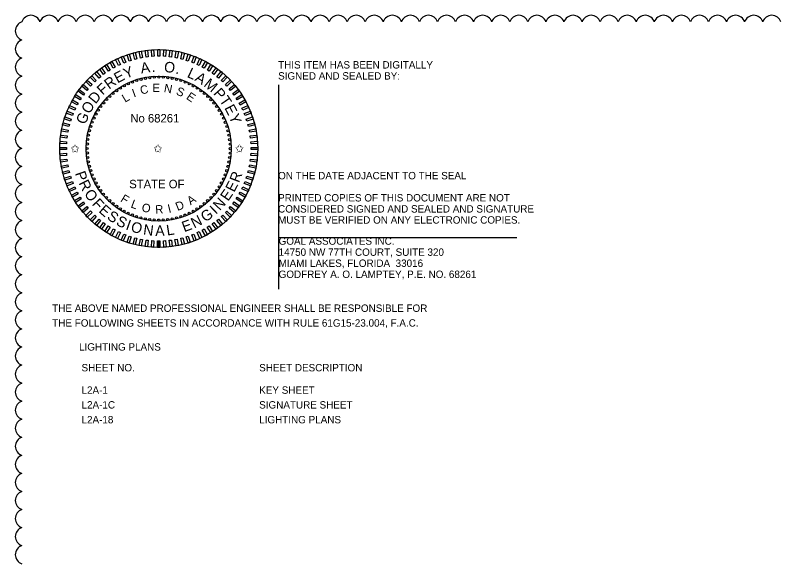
# Model space of a CAD drawing. Extents: x -811 to -790, y -2284 to -2178.
# Drawn here: x -810.85 to -803.6, y -2224.81 to -2219.62 of the extents above; entities that cross this region are included whole.
import ezdxf

# ---------------------------------------------------------------- set-up
doc = ezdxf.new("R2010")
doc.units = 0
for name, color, linetype in [('AdhocPoint_dp', 7, 'Continuous'), ('PlotBorder_dp', 7, 'Continuous'), ('TextMinor', 7, 'Continuous'), ('TextMisc', 7, 'Continuous'), ('TextShtNo', 7, 'Continuous'), ('TextTitle', 7, 'Continuous')]:
    doc.layers.add(name, color=color, linetype=linetype)

msp = doc.modelspace()

# ---------------------------------------------------------------- linework, layer by layer
at = {"layer": 'AdhocPoint_dp'}
for p, q in [((-808.3546, -2220.2766), (-808.3546, -2222.2113)), ((-808.3546, -2221.7213), (-806.0979, -2221.7213))]:
    msp.add_line(p, q, dxfattribs=at)
at = {"layer": 'TextMinor'}
for radius in [0.9375, 0.6875]:
    msp.add_circle((-809.4901, -2220.88), radius, dxfattribs=at)
at = {"layer": 'TextShtNo'}
for p, q in [((-809.5001, -2221.8175), (-809.5003, -2221.755)), ((-809.4901, -2221.8175), (-809.4903, -2221.755)), ((-809.4801, -2221.8174), (-809.4803, -2221.7549))]:
    msp.add_line(p, q, dxfattribs=at)
for points in [[(-809.6441, -2220.0185), (-809.6639, -2220.0223), (-809.6756, -2219.961), (-809.6558, -2219.9572)], [(-809.5897, -2220.0105), (-809.6097, -2220.0131), (-809.6175, -2219.9511), (-809.5975, -2219.9486)], [(-809.5349, -2220.006), (-809.555, -2220.0073), (-809.559, -2219.945), (-809.5388, -2219.9437)], [(-809.4799, -2220.0049), (-809.5001, -2220.0049), (-809.5001, -2219.9425), (-809.4799, -2219.9425)], [(-809.425, -2220.0073), (-809.4452, -2220.006), (-809.4412, -2219.9437), (-809.4211, -2219.945)], [(-809.3703, -2220.0131), (-809.3904, -2220.0106), (-809.3825, -2219.9486), (-809.3625, -2219.9512)], [(-809.3162, -2220.0223), (-809.336, -2220.0186), (-809.3243, -2219.9572), (-809.3045, -2219.961)], [(-809.8535, -2220.0839), (-809.8717, -2220.0925), (-809.8983, -2220.036), (-809.8801, -2220.0274)], [(-809.8028, -2220.0626), (-809.8215, -2220.0701), (-809.8445, -2220.012), (-809.8258, -2220.0046)], [(-809.7508, -2220.0446), (-809.77, -2220.0508), (-809.7893, -2219.9915), (-809.7701, -2219.9852)], [(-809.6979, -2220.0299), (-809.7174, -2220.0349), (-809.7329, -2219.9744), (-809.7134, -2219.9694)], [(-809.2626, -2220.0349), (-809.2822, -2220.0299), (-809.2667, -2219.9695), (-809.2471, -2219.9745)], [(-809.21, -2220.0509), (-809.2292, -2220.0447), (-809.2099, -2219.9853), (-809.1907, -2219.9915)], [(-809.1585, -2220.0701), (-809.1773, -2220.0627), (-809.1543, -2220.0046), (-809.1355, -2220.0121)], [(-809.1083, -2220.0925), (-809.1266, -2220.0839), (-809.1, -2220.0274), (-809.0817, -2220.036)], [(-809.9504, -2220.1357), (-809.9674, -2220.1465), (-810.0009, -2220.0938), (-809.9838, -2220.083)], [(-809.9027, -2220.1083), (-809.9204, -2220.118), (-809.9505, -2220.0633), (-809.9328, -2220.0535)], [(-809.0596, -2220.1181), (-809.0773, -2220.1083), (-809.0473, -2220.0536), (-809.0296, -2220.0634)], [(-809.0127, -2220.1466), (-809.0297, -2220.1358), (-808.9962, -2220.0831), (-808.9792, -2220.0939)], [(-810.04, -2220.1992), (-810.0556, -2220.2121), (-810.0954, -2220.164), (-810.0798, -2220.1511)], [(-809.9962, -2220.1661), (-810.0125, -2220.1779), (-810.0492, -2220.1274), (-810.0329, -2220.1155)], [(-808.9676, -2220.178), (-808.9839, -2220.1662), (-808.9472, -2220.1156), (-808.9308, -2220.1275)], [(-808.9245, -2220.2122), (-808.9401, -2220.1994), (-808.9003, -2220.1512), (-808.8847, -2220.1641)], [(-810.121, -2220.2735), (-810.1348, -2220.2882), (-810.1804, -2220.2455), (-810.1665, -2220.2308)], [(-810.0817, -2220.2351), (-810.0964, -2220.2489), (-810.1392, -2220.2034), (-810.1244, -2220.1896)], [(-808.8837, -2220.2491), (-808.8984, -2220.2352), (-808.8557, -2220.1897), (-808.841, -2220.2035)], [(-808.8453, -2220.2884), (-808.8591, -2220.2737), (-808.8136, -2220.2309), (-808.7998, -2220.2456)], [(-810.192, -2220.3574), (-810.2039, -2220.3737), (-810.2544, -2220.337), (-810.2426, -2220.3207)], [(-810.1579, -2220.3143), (-810.1707, -2220.3299), (-810.2188, -2220.2901), (-810.206, -2220.2745)], [(-808.8094, -2220.33), (-808.8223, -2220.3145), (-808.7742, -2220.2747), (-808.7613, -2220.2902)], [(-808.7762, -2220.3739), (-808.7881, -2220.3575), (-808.7376, -2220.3208), (-808.7257, -2220.3372)], [(-810.2235, -2220.4025), (-810.2343, -2220.4195), (-810.287, -2220.3861), (-810.2762, -2220.369)], [(-808.7459, -2220.4197), (-808.7567, -2220.4026), (-808.7039, -2220.3692), (-808.6931, -2220.3862)], [(-810.252, -2220.4495), (-810.2617, -2220.4672), (-810.3164, -2220.4371), (-810.3067, -2220.4194)], [(-808.7184, -2220.4673), (-808.7281, -2220.4496), (-808.6734, -2220.4196), (-808.6637, -2220.4373)], [(-810.3, -2220.5484), (-810.3074, -2220.5671), (-810.3654, -2220.5441), (-810.358, -2220.5254)], [(-810.2775, -2220.4982), (-810.2861, -2220.5164), (-810.3426, -2220.4898), (-810.334, -2220.4716)], [(-808.694, -2220.5166), (-808.7026, -2220.4983), (-808.6461, -2220.4718), (-808.6375, -2220.49)], [(-808.6728, -2220.5673), (-808.6802, -2220.5485), (-808.6222, -2220.5256), (-808.6147, -2220.5443)], [(-810.3192, -2220.5999), (-810.3254, -2220.6191), (-810.3848, -2220.5998), (-810.3786, -2220.5806)], [(-808.6548, -2220.6192), (-808.661, -2220.6), (-808.6016, -2220.5808), (-808.5954, -2220.5999)], [(-810.3351, -2220.6525), (-810.3401, -2220.672), (-810.4006, -2220.6565), (-810.3956, -2220.637)], [(-808.64, -2220.6722), (-808.6451, -2220.6527), (-808.5846, -2220.6371), (-808.5796, -2220.6567)], [(-810.357, -2220.7602), (-810.3595, -2220.7802), (-810.4215, -2220.7724), (-810.4189, -2220.7524)], [(-810.3477, -2220.706), (-810.3515, -2220.7258), (-810.4129, -2220.7141), (-810.4091, -2220.6943)], [(-808.6287, -2220.726), (-808.6325, -2220.7062), (-808.5711, -2220.6945), (-808.5673, -2220.7143)], [(-808.6207, -2220.7804), (-808.6232, -2220.7604), (-808.5613, -2220.7525), (-808.5588, -2220.7726)], [(-810.3628, -2220.8148), (-810.3641, -2220.835), (-810.4264, -2220.8311), (-810.4251, -2220.8109)], [(-808.6162, -2220.8352), (-808.6174, -2220.815), (-808.5551, -2220.8111), (-808.5539, -2220.8313)], [(-810.3652, -2220.8698), (-810.3652, -2220.89), (-810.4276, -2220.89), (-810.4276, -2220.8698)], [(-808.6151, -2220.8901), (-808.6151, -2220.87), (-808.5527, -2220.87), (-808.5527, -2220.8901)], [(-810.3641, -2220.9247), (-810.3628, -2220.9449), (-810.4251, -2220.9488), (-810.4264, -2220.9287)], [(-808.6175, -2220.9451), (-808.6162, -2220.9249), (-808.5539, -2220.9288), (-808.5551, -2220.949)], [(-810.3595, -2220.9795), (-810.357, -2220.9995), (-810.4189, -2221.0074), (-810.4215, -2220.9873)], [(-810.3516, -2221.0339), (-810.3478, -2221.0537), (-810.4091, -2221.0654), (-810.4129, -2221.0456)], [(-808.6325, -2221.0539), (-808.6287, -2221.0341), (-808.5674, -2221.0458), (-808.5712, -2221.0656)], [(-808.6233, -2220.9997), (-808.6207, -2220.9797), (-808.5588, -2220.9875), (-808.5613, -2221.0076)], [(-810.3402, -2221.0877), (-810.3352, -2221.1073), (-810.3957, -2221.1228), (-810.4007, -2221.1032)], [(-808.6451, -2221.1074), (-808.6401, -2221.0879), (-808.5796, -2221.1034), (-808.5846, -2221.123)], [(-810.3255, -2221.1407), (-810.3192, -2221.1599), (-810.3786, -2221.1792), (-810.3849, -2221.16)], [(-810.3075, -2221.1926), (-810.3, -2221.2114), (-810.3581, -2221.2344), (-810.3655, -2221.2156)], [(-808.6803, -2221.2115), (-808.6729, -2221.1928), (-808.6148, -2221.2158), (-808.6222, -2221.2345)], [(-808.6611, -2221.16), (-808.6548, -2221.1408), (-808.5954, -2221.1601), (-808.6017, -2221.1793)], [(-810.2862, -2221.2433), (-810.2776, -2221.2616), (-810.3341, -2221.2882), (-810.3427, -2221.2699)], [(-808.7027, -2221.2617), (-808.6941, -2221.2435), (-808.6376, -2221.2701), (-808.6462, -2221.2883)], [(-810.2618, -2221.2926), (-810.2521, -2221.3103), (-810.3068, -2221.3403), (-810.3165, -2221.3227)], [(-808.7282, -2221.3104), (-808.7185, -2221.2927), (-808.6638, -2221.3228), (-808.6735, -2221.3405)], [(-810.2344, -2221.3402), (-810.2236, -2221.3573), (-810.2763, -2221.3907), (-810.2871, -2221.3737)], [(-810.204, -2221.386), (-810.1922, -2221.4024), (-810.2427, -2221.4391), (-810.2545, -2221.4227)], [(-808.7882, -2221.4025), (-808.7763, -2221.3862), (-808.7258, -2221.4229), (-808.7377, -2221.4392)], [(-808.7568, -2221.3574), (-808.746, -2221.3404), (-808.6932, -2221.3738), (-808.704, -2221.3909)], [(-810.1708, -2221.4299), (-810.158, -2221.4454), (-810.2061, -2221.4852), (-810.2189, -2221.4697)], [(-810.135, -2221.4715), (-810.1211, -2221.4862), (-810.1667, -2221.529), (-810.1805, -2221.5143)], [(-808.8592, -2221.4864), (-808.8454, -2221.4717), (-808.7999, -2221.5144), (-808.8137, -2221.5291)], [(-808.8224, -2221.4456), (-808.8095, -2221.43), (-808.7614, -2221.4698), (-808.7743, -2221.4854)], [(-810.0965, -2221.5109), (-810.0818, -2221.5247), (-810.1246, -2221.5702), (-810.1393, -2221.5564)], [(-810.0557, -2221.5477), (-810.0402, -2221.5606), (-810.08, -2221.6087), (-810.0955, -2221.5958)], [(-808.9402, -2221.5607), (-808.9247, -2221.5478), (-808.8848, -2221.5959), (-808.9004, -2221.6088)], [(-808.8985, -2221.5248), (-808.8838, -2221.511), (-808.8411, -2221.5565), (-808.8558, -2221.5703)], [(-810.0127, -2221.5819), (-809.9964, -2221.5937), (-810.0331, -2221.6443), (-810.0494, -2221.6324)], [(-809.9676, -2221.6133), (-809.9505, -2221.6241), (-809.984, -2221.6768), (-810.001, -2221.666)], [(-809.0299, -2221.6242), (-809.0128, -2221.6134), (-808.9794, -2221.6661), (-808.9964, -2221.6769)], [(-808.984, -2221.5939), (-808.9677, -2221.582), (-808.931, -2221.6325), (-808.9473, -2221.6444)], [(-809.9206, -2221.6418), (-809.9029, -2221.6516), (-809.933, -2221.7063), (-809.9507, -2221.6966)], [(-809.8719, -2221.6674), (-809.8536, -2221.676), (-809.8802, -2221.7325), (-809.8985, -2221.7239)], [(-809.8217, -2221.6898), (-809.8029, -2221.6972), (-809.8259, -2221.7553), (-809.8447, -2221.7478)], [(-809.1775, -2221.6973), (-809.1587, -2221.6899), (-809.1357, -2221.7479), (-809.1545, -2221.7553)], [(-809.1268, -2221.676), (-809.1085, -2221.6674), (-809.0819, -2221.7239), (-809.1002, -2221.7325)], [(-809.0775, -2221.6517), (-809.0598, -2221.6419), (-809.0297, -2221.6966), (-809.0474, -2221.7064)], [(-809.7702, -2221.709), (-809.751, -2221.7152), (-809.7703, -2221.7746), (-809.7895, -2221.7684)], [(-809.7176, -2221.725), (-809.698, -2221.73), (-809.7136, -2221.7905), (-809.7331, -2221.7854)], [(-809.6641, -2221.7376), (-809.6443, -2221.7414), (-809.656, -2221.8027), (-809.6758, -2221.7989)], [(-809.6099, -2221.7468), (-809.5899, -2221.7493), (-809.5977, -2221.8113), (-809.6177, -2221.8088)], [(-809.5552, -2221.7526), (-809.5351, -2221.7539), (-809.539, -2221.8162), (-809.5592, -2221.8149)], [(-809.5003, -2221.755), (-809.4801, -2221.755), (-809.4801, -2221.8174), (-809.5003, -2221.8174)], [(-809.4453, -2221.7539), (-809.4252, -2221.7526), (-809.4213, -2221.8149), (-809.4414, -2221.8162)], [(-809.3906, -2221.7494), (-809.3705, -2221.7468), (-809.3627, -2221.8088), (-809.3827, -2221.8113)], [(-809.3362, -2221.7414), (-809.3163, -2221.7376), (-809.3046, -2221.7989), (-809.3245, -2221.8027)], [(-809.2824, -2221.73), (-809.2628, -2221.725), (-809.2473, -2221.7855), (-809.2668, -2221.7905)], [(-809.2294, -2221.7153), (-809.2102, -2221.7091), (-809.1909, -2221.7685), (-809.2101, -2221.7747)]]:
    msp.add_lwpolyline(points, close=True, dxfattribs=at)
for centre in [(-809.739, -2220.2499), (-809.6989, -2220.2355), (-809.6581, -2220.2236), (-809.6165, -2220.2144), (-809.5745, -2220.2078), (-809.5321, -2220.2038), (-809.4896, -2220.2025), (-809.447, -2220.2039), (-809.4047, -2220.2079), (-809.3626, -2220.2146), (-809.3211, -2220.2239), (-809.2802, -2220.2358), (-809.2402, -2220.2503), (-809.8879, -2220.3315), (-809.8527, -2220.3076), (-809.816, -2220.286), (-809.7781, -2220.2667), (-809.2012, -2220.2672), (-809.1633, -2220.2866), (-809.1266, -2220.3083), (-809.0915, -2220.3322), (-809.9535, -2220.3857), (-809.9215, -2220.3576), (-809.0579, -2220.3583), (-809.026, -2220.3865), (-810.0118, -2220.4477), (-809.9836, -2220.4158), (-808.9959, -2220.4166), (-808.9678, -2220.4486), (-810.0618, -2220.5165), (-810.0379, -2220.4813), (-808.9417, -2220.4822), (-808.9178, -2220.5174), (-810.1029, -2220.591), (-810.0835, -2220.5531), (-808.8962, -2220.5541), (-808.8769, -2220.592), (-810.1343, -2220.6701), (-810.1198, -2220.63), (-808.86, -2220.6311), (-808.8456, -2220.6711), (-810.1555, -2220.7525), (-810.1462, -2220.7109), (-808.8338, -2220.712), (-808.8245, -2220.7536), (-810.1662, -2220.8369), (-810.1622, -2220.7945), (-808.8179, -2220.7956), (-808.814, -2220.838), (-810.1676, -2220.8794), (-808.8127, -2220.8805), (-810.1663, -2220.9219), (-810.1623, -2220.9643), (-808.8181, -2220.9654), (-808.814, -2220.9231), (-810.1557, -2221.0063), (-810.1464, -2221.0479), (-808.8341, -2221.049), (-808.8248, -2221.0075), (-810.1346, -2221.0888), (-810.1202, -2221.1288), (-808.8604, -2221.1299), (-808.846, -2221.0898), (-810.1034, -2221.1679), (-808.8774, -2221.1689), (-810.0841, -2221.2058), (-810.0624, -2221.2425), (-808.9184, -2221.2434), (-808.8967, -2221.2068), (-810.0385, -2221.2777), (-810.0125, -2221.3114), (-809.9844, -2221.3433), (-808.9967, -2221.3441), (-808.9685, -2221.3122), (-808.9424, -2221.2786), (-809.9543, -2221.3734), (-809.9224, -2221.4016), (-809.0587, -2221.4023), (-809.0268, -2221.3742), (-809.8888, -2221.4277), (-809.8536, -2221.4517), (-809.817, -2221.4734), (-809.7791, -2221.4927), (-809.2022, -2221.4932), (-809.1642, -2221.4739), (-809.1276, -2221.4523), (-809.0924, -2221.4284), (-809.74, -2221.5096), (-809.7, -2221.5241), (-809.6591, -2221.536), (-809.6176, -2221.5453), (-809.5756, -2221.552), (-809.5332, -2221.5561), (-809.4901, -2221.5575), (-809.4481, -2221.5561), (-809.4058, -2221.5522), (-809.3637, -2221.5455), (-809.3222, -2221.5363), (-809.2813, -2221.5244), (-809.2413, -2221.5101)]:
    msp.add_circle(centre, 0.01, dxfattribs=at)
at = {"layer": 'TextTitle'}
for centre, start, end in [((-810.7002, -2219.707), 17.5, 162.5), ((-810.5291, -2219.707), 17.5, 162.5), ((-810.358, -2219.707), 17.5, 162.5), ((-810.1868, -2219.707), 17.5, 162.5), ((-810.0157, -2219.707), 17.5, 162.5), ((-809.8446, -2219.707), 17.5, 162.5), ((-809.6735, -2219.707), 17.5, 162.5), ((-809.5024, -2219.707), 17.5, 162.5), ((-809.3312, -2219.707), 17.5, 162.5), ((-809.1601, -2219.707), 17.5, 162.5), ((-808.989, -2219.707), 17.5, 162.5), ((-808.8179, -2219.707), 17.5, 162.5), ((-808.6467, -2219.707), 17.5, 162.5), ((-808.4756, -2219.707), 17.5, 162.5), ((-808.3045, -2219.707), 17.5, 162.5), ((-808.1334, -2219.707), 17.5, 162.5), ((-807.9622, -2219.707), 17.5, 162.5), ((-807.7911, -2219.707), 17.5, 162.5), ((-807.62, -2219.707), 17.5, 162.5), ((-807.4489, -2219.707), 17.5, 162.5), ((-807.2778, -2219.707), 17.5, 162.5), ((-807.1066, -2219.707), 17.5, 162.5), ((-806.9355, -2219.707), 17.5, 162.5), ((-806.7644, -2219.707), 17.5, 162.5), ((-806.5933, -2219.707), 17.5, 162.5), ((-806.4221, -2219.707), 17.5, 162.5), ((-806.251, -2219.707), 17.5, 162.5), ((-806.0799, -2219.707), 17.5, 162.5), ((-805.9088, -2219.707), 17.5, 162.5), ((-805.7377, -2219.707), 17.5, 162.5), ((-805.5665, -2219.707), 17.5, 162.5), ((-805.3954, -2219.707), 17.5, 162.5), ((-805.2243, -2219.707), 17.5, 162.5), ((-805.0532, -2219.707), 17.5, 162.5), ((-804.882, -2219.707), 17.5, 162.5), ((-804.7109, -2219.707), 17.5, 162.5), ((-804.5398, -2219.707), 17.5, 162.5), ((-804.3687, -2219.707), 17.5, 162.5), ((-804.1976, -2219.707), 17.5, 162.5), ((-804.0264, -2219.707), 17.5, 162.5), ((-803.8553, -2219.707), 17.5, 162.5), ((-803.6842, -2219.707), 17.5, 162.5), ((-810.7588, -2219.7655), 107.5, 252.5), ((-810.7588, -2219.9367), 107.5, 252.5), ((-810.7588, -2220.1078), 107.5, 252.5), ((-810.7588, -2220.2789), 107.5, 252.5), ((-810.7588, -2220.45), 107.5, 252.5), ((-810.7588, -2220.6212), 107.5, 252.5), ((-810.7588, -2220.7923), 107.5, 252.5), ((-810.7588, -2220.9634), 107.5, 252.5), ((-810.7588, -2221.1345), 107.5, 252.5), ((-810.7588, -2221.3057), 107.5, 252.5), ((-810.7588, -2221.4768), 107.5, 252.5), ((-810.7588, -2221.6479), 107.5, 252.5), ((-810.7588, -2221.819), 107.5, 252.5), ((-810.7588, -2221.9901), 107.5, 252.5), ((-810.7588, -2222.1613), 107.5, 252.5), ((-810.7588, -2222.3324), 107.5, 252.5), ((-810.7588, -2222.5035), 107.5, 252.5), ((-810.7588, -2222.6746), 107.5, 252.5), ((-810.7588, -2222.8458), 107.5, 252.5), ((-810.7588, -2223.0169), 107.5, 252.5), ((-810.7588, -2223.188), 107.5, 252.5), ((-810.7588, -2223.3591), 107.5, 252.5), ((-810.7588, -2223.5302), 107.5, 252.5), ((-810.7588, -2223.7014), 107.5, 252.5), ((-810.7588, -2223.8725), 107.5, 252.5), ((-810.7588, -2224.0436), 107.5, 252.5), ((-810.7588, -2224.2147), 107.5, 252.5), ((-810.7588, -2224.3859), 107.5, 252.5), ((-810.7588, -2224.557), 107.5, 252.5), ((-810.7588, -2224.7281), 107.5, 252.5)]:
    msp.add_arc(centre, 0.0897, start, end, dxfattribs=at)

# ---------------------------------------------------------------- texts
at = {"layer": 'PlotBorder_dp'}
for s, p in [('THIS ITEM HAS BEEN DIGITALLY', (-808.3596, -2220.1214)), ('SIGNED AND SEALED BY:', (-808.3596, -2220.2264)), ('ON THE DATE ADJACENT TO THE SEAL', (-808.3596, -2221.1714)), ('PRINTED COPIES OF THIS DOCUMENT ARE NOT ', (-808.3596, -2221.3814)), ('CONSIDERED SIGNED AND SEALED AND SIGNATURE ', (-808.3596, -2221.4864)), ('MUST BE VERIFIED ON ANY ELECTRONIC COPIES.', (-808.3596, -2221.5914)), ('GOAL ASSOCIATES INC.', (-808.3546, -2221.7913)), ('14750 NW 77TH COURT, SUITE 320', (-808.3546, -2221.8963)), ('MIAMI LAKES, FLORIDA  33016', (-808.3546, -2222.0013)), ('GODFREY A. O. LAMPTEY, P.E. NO. 68261', (-808.3546, -2222.1063)), ('THE ABOVE NAMED PROFESSIONAL ENGINEER SHALL BE RESPONSIBLE FOR ', (-810.4987, -2222.4274)), ('THE FOLLOWING SHEETS IN ACCORDANCE WITH RULE 61G15-23.004, F.A.C.', (-810.4987, -2222.5674)), ('LIGHTING PLANS', (-810.245, -2222.7944))]:
    msp.add_text(s, height=0.07, dxfattribs=at).set_placement(p)
at = {"layer": 'TextMisc'}
for s, p in [('SHEET NO.', (-810.2215, -2222.9914)), ('SHEET DESCRIPTION', (-808.5387, -2222.9914)), ('L2A-1', (-810.2215, -2223.2036)), ('KEY SHEET', (-808.5387, -2223.2036)), ('L2A-1C', (-810.2215, -2223.3436)), ('SIGNATURE SHEET', (-808.5387, -2223.3436)), ('L2A-18', (-810.2215, -2223.4836)), ('LIGHTING PLANS', (-808.5387, -2223.4836))]:
    msp.add_text(s, height=0.07, dxfattribs=at).set_placement(p)
at = {"layer": 'TextShtNo'}
for s, height, rotation, p in [('Y', 0.1, 21.06329, (-809.8021, -2220.2205)), ('A', 0.1, 8.80884, (-809.6551, -2220.1693)), ('O', 0.1, 352.18771, (-809.4449, -2220.1518)), ('E', 0.1, 28.10553, (-809.8806, -2220.2638)), ('.', 0.1, 1.04184, (-809.5575, -2220.1536)), ('.', 0.1, 343.52684, (-809.3358, -2220.167)), ('L', 0.1, 334.67271, (-809.2279, -2220.1992)), ('A', 0.1, 328.40959, (-809.1552, -2220.2319)), ('R', 0.1, 35.92688, (-809.9609, -2220.3226)), ('M', 0.1, 320.6426, (-809.0707, -2220.2831)), ('F', 0.1, 42.37723, (-810.0205, -2220.3791)), ('I', 0.08, 20.01168, (-809.7258, -2220.3959)), ('C', 0.08, 12.20255, (-809.6579, -2220.3684)), ('E', 0.08, 0.41861, (-809.5498, -2220.3449)), ('N', 0.08, 349.29143, (-809.4455, -2220.3434)), ('S', 0.08, 337.02207, (-809.3325, -2220.3652)), ('P', 0.1, 311.19658, (-808.9784, -2220.36)), ('D', 0.1, 50.8569, (-810.0886, -2220.4627)), ('L', 0.08, 30.40215, (-809.8093, -2220.4463)), ('E', 0.08, 325.86633, (-809.2358, -2220.4054)), ('T', 0.1, 304.45632, (-808.9209, -2220.4237)), ('O', 0.1, 59.51777, (-810.1446, -2220.5576)), ('E', 0.1, 297.63152, (-808.8707, -2220.4946)), ('Y', 0.1, 290.58928, (-808.8281, -2220.5734)), ('G', 0.1, 68.0518, (-810.1851, -2220.6583)), ('P', 0.1, 289.40551, (-810.2848, -2221.1145)), ('R', 0.1, 69.5134, (-808.7299, -2221.2097)), ('R', 0.1, 296.14576, (-810.2518, -2221.2062)), ('E', 0.1, 62.47116, (-808.7761, -2221.3004)), ('E', 0.1, 55.42892, (-808.833, -2221.3847)), ('O', 0.1, 303.96711, (-810.2003, -2221.3068)), ('F', 0.08, 328.72408, (-809.8582, -2221.3765)), ('A', 0.08, 34.49917, (-809.1883, -2221.4194)), ('F', 0.1, 312.62798, (-810.1279, -2221.4089)), ('E', 0.1, 319.07833, (-810.0645, -2221.4772)), ('L', 0.08, 339.29159, (-809.7609, -2221.4356)), ('O', 0.08, 349.68206, (-809.6562, -2221.4753)), ('I', 0.08, 14.20366, (-809.3941, -2221.4906)), ('D', 0.08, 22.01279, (-809.312, -2221.4719)), ('N', 0.1, 47.17876, (-808.9123, -2221.4738)), ('S', 0.1, 326.12056, (-809.9869, -2221.5431)), ('R', 0.08, 2.33977, (-809.5217, -2221.4973)), ('G', 0.1, 35.11153, (-809.0492, -2221.5815)), ('I', 0.1, 43.64556, (-808.9499, -2221.5083)), ('S', 0.1, 333.193, (-809.9015, -2221.5992)), ('I', 0.1, 340.26543, (-809.8098, -2221.6444)), ('E', 0.1, 19.81912, (-809.2498, -2221.6729)), ('N', 0.1, 26.86136, (-809.1544, -2221.6375)), ('O', 0.1, 343.79863, (-809.7621, -2221.6627)), ('N', 0.1, 352.45949, (-809.6411, -2221.6947)), ('A', 0.1, 0.70966, (-809.5227, -2221.7079)), ('L', 0.1, 8.47665, (-809.4105, -2221.7047))]:
    msp.add_text(s, height=height, rotation=rotation, dxfattribs=at).set_placement(p)
for s, p in [('No 68261', (-809.7591, -2220.6327)), ('✩', (-810.3251, -2220.9179)), ('✩', (-809.5404, -2220.9179)), ('✩', (-808.7685, -2220.9179)), ('STATE OF', (-809.7698, -2221.2562))]:
    msp.add_text(s, height=0.08, dxfattribs=at).set_placement(p)

doc.saveas('drawing.dxf')
